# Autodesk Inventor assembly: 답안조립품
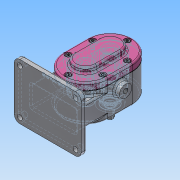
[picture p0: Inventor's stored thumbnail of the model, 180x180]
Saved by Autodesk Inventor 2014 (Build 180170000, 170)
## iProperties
Created: 2020-09
Part Number: 답안조립품
Document SubType Name: Assembly
Designer: net
Author: net
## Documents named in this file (11)
- C:\Users\net\Desktop\답안조립품.iam
- C:\Users\net\Desktop\부품.ipt
- C:\Users\net\Desktop\딱따구리\메인축.ipt
- C:\Users\net\Desktop\딱따구리\베어링부시.ipt
- C:\Users\net\Desktop\딱따구리\서브축.ipt
- C:\Users\net\Desktop\딱따구리\스퍼기어.ipt
- C:\Users\net\Desktop\딱따구리\키 6 x 6 x 18.ipt
- C:\Users\net\Desktop\딱따구리\개스킷.ipt
- C:\Users\net\Desktop\딱따구리\볼트 M5.ipt
- C:\Users\net\Desktop\딱따구리\오일 실 16 28 7.ipt
- C:\Users\net\Desktop\딱따구리\커버.ipt
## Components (1 placed, 1 different names)
1. 개스킷:1
